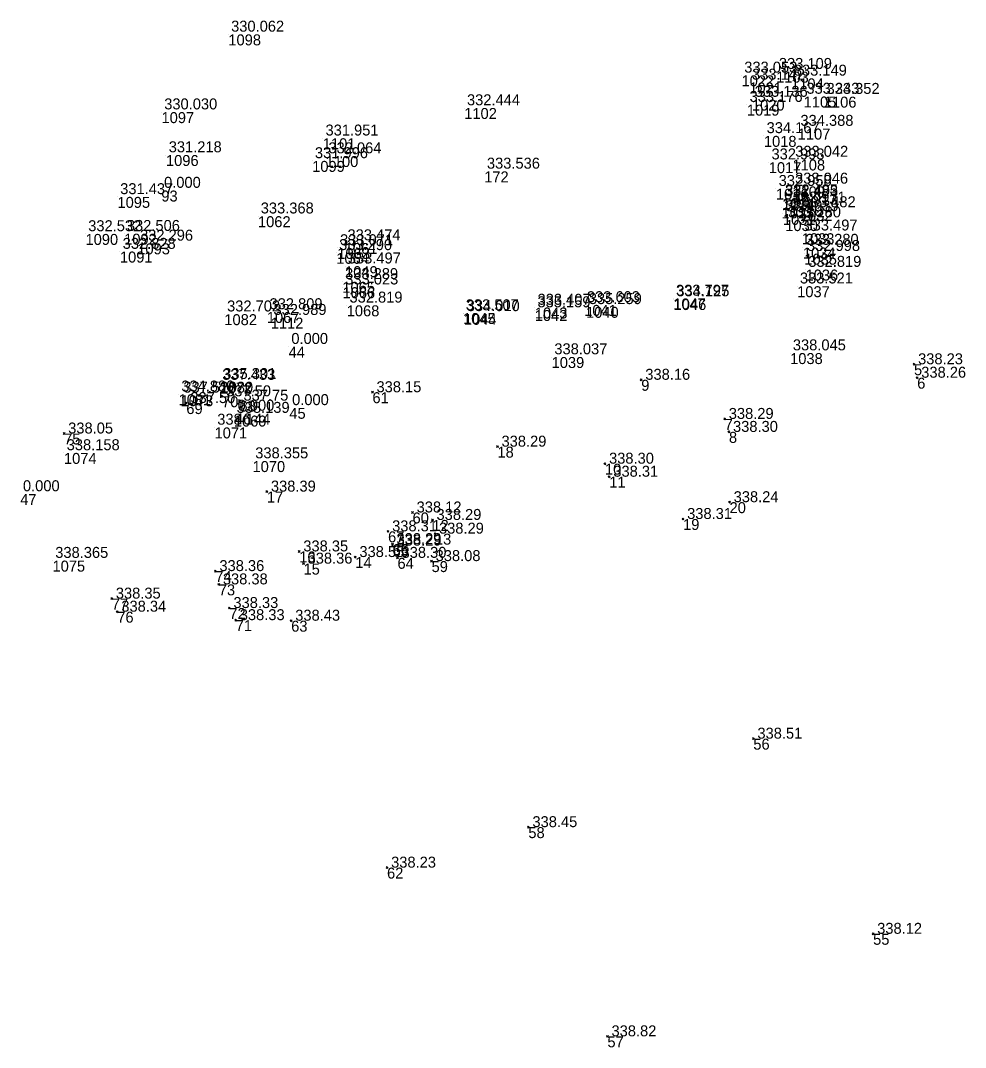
# Model space of a CAD drawing. Extents: x -829398 to -819400, y -1074439 to -1067977.
# Drawn here: x -825510.3 to -825406.9, y -1070192.8 to -1070080.5 of the extents above; entities that cross this region are included whole.
import ezdxf

# ---------------------------------------------------------------- set-up
doc = ezdxf.new("R2010")
doc.units = 0
doc.layers.add('Vrstva 60', color=7, linetype='Continuous')
doc.layers.add('Vrstva 61', color=7, linetype='Continuous')

msp = doc.modelspace()

# ---------------------------------------------------------------- linework, layer by layer
at = {"layer": 'Vrstva 60'}
for p, q in [((-825487.568, -1070081.975), (-825487.568, -1070081.975)), ((-825431.407, -1070086.457), (-825431.407, -1070086.457)), ((-825427.618, -1070086.054), (-825427.618, -1070086.054)), ((-825425.983, -1070086.788), (-825425.983, -1070086.788)), ((-825430.563, -1070087.234), (-825430.563, -1070087.234)), ((-825430.264, -1070089.105), (-825430.264, -1070089.105)), ((-825424.609, -1070088.772), (-825424.609, -1070088.772)), ((-825422.398, -1070088.786), (-825422.398, -1070088.786)), ((-825461.754, -1070090.029), (-825461.754, -1070090.029)), ((-825430.827, -1070089.662), (-825430.827, -1070089.662)), ((-825494.888, -1070090.481), (-825494.888, -1070090.481)), ((-825425.259, -1070092.281), (-825425.259, -1070092.281)), ((-825477.236, -1070093.341), (-825477.236, -1070093.341)), ((-825428.961, -1070093.081), (-825428.961, -1070093.081)), ((-825494.396, -1070095.175), (-825494.396, -1070095.175)), ((-825478.397, -1070095.821), (-825478.397, -1070095.821)), ((-825476.919, -1070095.288), (-825476.919, -1070095.288)), ((-825428.427, -1070095.957), (-825428.427, -1070095.957)), ((-825425.834, -1070095.665), (-825425.834, -1070095.665)), ((-825459.572, -1070096.967), (-825459.572, -1070096.967)), ((-825494.907, -1070099.064), (-825494.907, -1070099.064)), ((-825427.645, -1070098.86), (-825427.645, -1070098.86)), ((-825425.845, -1070098.607), (-825425.845, -1070098.607)), ((-825499.707, -1070099.758), (-825499.707, -1070099.758)), ((-825426.948, -1070099.886), (-825426.948, -1070099.886)), ((-825426.938, -1070099.975), (-825426.938, -1070099.975)), ((-825427.014, -1070100.906), (-825427.014, -1070100.906)), ((-825426.885, -1070101.627), (-825426.885, -1070101.627)), ((-825426.112, -1070100.679), (-825426.112, -1070100.679)), ((-825425.016, -1070101.189), (-825425.016, -1070101.189)), ((-825484.326, -1070101.871), (-825484.326, -1070101.871)), ((-825426.628, -1070102.296), (-825426.628, -1070102.296)), ((-825503.207, -1070103.813), (-825503.207, -1070103.813)), ((-825498.975, -1070103.784), (-825498.975, -1070103.784)), ((-825424.811, -1070103.736), (-825424.811, -1070103.736)), ((-825497.536, -1070104.845), (-825497.536, -1070104.845)), ((-825474.83, -1070104.805), (-825474.83, -1070104.805)), ((-825499.44, -1070105.742), (-825499.44, -1070105.742)), ((-825475.754, -1070105.88), (-825475.754, -1070105.88)), ((-825475.646, -1070105.345), (-825475.646, -1070105.345)), ((-825424.692, -1070105.301), (-825424.692, -1070105.301)), ((-825424.54, -1070105.973), (-825424.54, -1070105.973)), ((-825474.796, -1070107.341), (-825474.796, -1070107.341)), ((-825424.399, -1070107.713), (-825424.399, -1070107.713)), ((-825475.093, -1070109.051), (-825475.093, -1070109.051)), ((-825425.318, -1070109.533), (-825425.318, -1070109.533)), ((-825475.076, -1070109.642), (-825475.076, -1070109.642)), ((-825474.615, -1070111.623), (-825474.615, -1070111.623)), ((-825448.63, -1070111.58), (-825448.63, -1070111.58)), ((-825448.423, -1070111.789), (-825448.423, -1070111.789)), ((-825438.879, -1070110.871), (-825438.879, -1070110.871)), ((-825438.836, -1070110.937), (-825438.836, -1070110.937)), ((-825488.009, -1070112.593), (-825488.009, -1070112.593)), ((-825483.362, -1070112.349), (-825483.362, -1070112.349)), ((-825461.883, -1070112.464), (-825461.883, -1070112.464)), ((-825461.785, -1070112.557), (-825461.785, -1070112.557)), ((-825454.039, -1070112.137), (-825454.039, -1070112.137)), ((-825454.029, -1070111.862), (-825454.029, -1070111.862)), ((-825482.931, -1070112.976), (-825482.931, -1070112.976)), ((-825480.978, -1070116.15), (-825480.978, -1070116.15)), ((-825452.192, -1070117.281), (-825452.192, -1070117.281)), ((-825426.09, -1070116.851), (-825426.09, -1070116.851)), ((-825412.529, -1070118.074), (-825412.629, -1070117.974)), ((-825412.529, -1070118.074), (-825412.629, -1070118.174)), ((-825412.529, -1070118.074), (-825412.429, -1070117.974)), ((-825412.529, -1070118.074), (-825412.429, -1070118.174)), ((-825412.183, -1070119.545), (-825412.283, -1070119.445)), ((-825412.183, -1070119.545), (-825412.283, -1070119.645)), ((-825412.183, -1070119.545), (-825412.083, -1070119.445)), ((-825412.183, -1070119.545), (-825412.083, -1070119.645)), ((-825488.538, -1070120.077), (-825488.538, -1070120.077)), ((-825488.432, -1070119.984), (-825488.432, -1070119.984)), ((-825442.383, -1070119.773), (-825442.483, -1070119.673)), ((-825442.383, -1070119.773), (-825442.483, -1070119.873)), ((-825442.383, -1070119.773), (-825442.283, -1070119.673)), ((-825442.383, -1070119.773), (-825442.283, -1070119.873)), ((-825493.018, -1070121.358), (-825493.018, -1070121.358)), ((-825492.798, -1070121.473), (-825492.798, -1070121.473)), ((-825488.259, -1070121.578), (-825488.359, -1070121.478)), ((-825488.259, -1070121.578), (-825488.359, -1070121.678)), ((-825488.259, -1070121.578), (-825488.159, -1070121.478)), ((-825488.259, -1070121.578), (-825488.159, -1070121.678)), ((-825471.803, -1070121.133), (-825471.903, -1070121.033)), ((-825471.803, -1070121.133), (-825471.903, -1070121.233)), ((-825471.803, -1070121.133), (-825471.703, -1070121.033)), ((-825471.803, -1070121.133), (-825471.703, -1070121.233)), ((-825492.17, -1070122.322), (-825492.27, -1070122.222)), ((-825492.17, -1070122.322), (-825492.27, -1070122.422)), ((-825492.17, -1070122.322), (-825492.07, -1070122.222)), ((-825492.17, -1070122.322), (-825492.07, -1070122.422)), ((-825486.362, -1070122.053), (-825486.462, -1070121.953)), ((-825486.362, -1070122.053), (-825486.462, -1070122.153)), ((-825486.362, -1070122.053), (-825486.262, -1070121.953)), ((-825486.362, -1070122.053), (-825486.262, -1070122.153)), ((-825480.896, -1070122.842), (-825480.896, -1070122.842)), ((-825486.968, -1070123.69), (-825486.968, -1070123.69)), ((-825486.857, -1070123.456), (-825486.857, -1070123.456)), ((-825433.25, -1070124.055), (-825433.35, -1070123.955)), ((-825433.25, -1070124.055), (-825433.35, -1070124.155)), ((-825433.25, -1070124.055), (-825433.15, -1070123.955)), ((-825433.25, -1070124.055), (-825433.15, -1070124.155)), ((-825489.084, -1070124.987), (-825489.084, -1070124.987)), ((-825505.546, -1070125.652), (-825505.646, -1070125.552)), ((-825505.546, -1070125.652), (-825505.646, -1070125.752)), ((-825505.546, -1070125.652), (-825505.446, -1070125.552)), ((-825505.546, -1070125.652), (-825505.446, -1070125.752)), ((-825432.783, -1070125.475), (-825432.883, -1070125.375)), ((-825432.783, -1070125.475), (-825432.883, -1070125.575)), ((-825432.783, -1070125.475), (-825432.683, -1070125.375)), ((-825432.783, -1070125.475), (-825432.683, -1070125.575)), ((-825458.121, -1070127.09), (-825458.221, -1070126.99)), ((-825458.121, -1070127.09), (-825458.221, -1070127.19)), ((-825458.121, -1070127.09), (-825458.021, -1070126.99)), ((-825458.121, -1070127.09), (-825458.021, -1070127.19)), ((-825505.564, -1070127.779), (-825505.564, -1070127.779)), ((-825484.929, -1070128.668), (-825484.929, -1070128.668)), ((-825446.352, -1070128.954), (-825446.452, -1070128.854)), ((-825446.352, -1070128.954), (-825446.452, -1070129.054)), ((-825446.352, -1070128.954), (-825446.252, -1070128.854)), ((-825446.352, -1070128.954), (-825446.252, -1070129.054)), ((-825445.885, -1070130.381), (-825445.985, -1070130.281)), ((-825445.885, -1070130.381), (-825445.985, -1070130.481)), ((-825445.885, -1070130.381), (-825445.785, -1070130.281)), ((-825445.885, -1070130.381), (-825445.785, -1070130.481)), ((-825483.357, -1070132.007), (-825483.457, -1070131.907)), ((-825483.357, -1070132.007), (-825483.457, -1070132.107)), ((-825483.357, -1070132.007), (-825483.257, -1070131.907)), ((-825483.357, -1070132.007), (-825483.257, -1070132.107)), ((-825432.715, -1070133.167), (-825432.815, -1070133.067)), ((-825432.715, -1070133.167), (-825432.615, -1070133.067)), ((-825467.411, -1070134.292), (-825467.511, -1070134.192)), ((-825467.411, -1070134.292), (-825467.311, -1070134.192)), ((-825432.715, -1070133.167), (-825432.815, -1070133.267)), ((-825432.715, -1070133.167), (-825432.615, -1070133.267)), ((-825467.411, -1070134.292), (-825467.511, -1070134.392)), ((-825467.411, -1070134.292), (-825467.311, -1070134.392)), ((-825465.236, -1070135.109), (-825465.336, -1070135.009)), ((-825465.236, -1070135.109), (-825465.336, -1070135.209)), ((-825465.236, -1070135.109), (-825465.136, -1070135.009)), ((-825465.236, -1070135.109), (-825465.136, -1070135.209)), ((-825437.806, -1070135.008), (-825437.906, -1070134.908)), ((-825437.806, -1070135.008), (-825437.906, -1070135.108)), ((-825437.806, -1070135.008), (-825437.706, -1070134.908)), ((-825437.806, -1070135.008), (-825437.706, -1070135.108)), ((-825470.092, -1070136.359), (-825470.192, -1070136.259)), ((-825470.092, -1070136.359), (-825470.192, -1070136.459)), ((-825470.092, -1070136.359), (-825469.992, -1070136.259)), ((-825470.092, -1070136.359), (-825469.992, -1070136.459)), ((-825464.962, -1070136.611), (-825465.062, -1070136.511)), ((-825464.962, -1070136.611), (-825464.862, -1070136.511)), ((-825464.962, -1070136.611), (-825465.062, -1070136.711)), ((-825464.962, -1070136.611), (-825464.862, -1070136.711)), ((-825479.815, -1070138.556), (-825479.915, -1070138.456)), ((-825479.815, -1070138.556), (-825479.915, -1070138.656)), ((-825479.815, -1070138.556), (-825479.715, -1070138.456)), ((-825479.815, -1070138.556), (-825479.715, -1070138.656)), ((-825469.612, -1070137.755), (-825469.712, -1070137.655)), ((-825469.612, -1070137.755), (-825469.712, -1070137.855)), ((-825469.595, -1070137.915), (-825469.695, -1070137.815)), ((-825469.595, -1070137.915), (-825469.695, -1070138.015)), ((-825469.612, -1070137.755), (-825469.512, -1070137.655)), ((-825469.612, -1070137.755), (-825469.512, -1070137.855)), ((-825469.595, -1070137.915), (-825469.495, -1070137.815)), ((-825469.595, -1070137.915), (-825469.495, -1070138.015)), ((-825506.816, -1070139.563), (-825506.816, -1070139.563)), ((-825479.344, -1070139.892), (-825479.444, -1070139.792)), ((-825479.344, -1070139.892), (-825479.444, -1070139.992)), ((-825479.344, -1070139.892), (-825479.244, -1070139.792)), ((-825479.344, -1070139.892), (-825479.244, -1070139.992)), ((-825473.676, -1070139.171), (-825473.776, -1070139.071)), ((-825473.676, -1070139.171), (-825473.776, -1070139.271)), ((-825473.676, -1070139.171), (-825473.576, -1070139.071)), ((-825473.676, -1070139.171), (-825473.576, -1070139.271)), ((-825469.061, -1070139.258), (-825469.161, -1070139.158)), ((-825469.061, -1070139.258), (-825469.161, -1070139.358)), ((-825469.061, -1070139.258), (-825468.961, -1070139.158)), ((-825469.061, -1070139.258), (-825468.961, -1070139.358)), ((-825465.33, -1070139.615), (-825465.43, -1070139.515)), ((-825465.33, -1070139.615), (-825465.43, -1070139.715)), ((-825465.33, -1070139.615), (-825465.23, -1070139.515)), ((-825465.33, -1070139.615), (-825465.23, -1070139.715)), ((-825488.995, -1070140.71), (-825489.095, -1070140.61)), ((-825488.995, -1070140.71), (-825489.095, -1070140.81)), ((-825488.995, -1070140.71), (-825488.895, -1070140.61)), ((-825488.995, -1070140.71), (-825488.895, -1070140.81)), ((-825488.617, -1070142.164), (-825488.717, -1070142.064)), ((-825488.617, -1070142.164), (-825488.517, -1070142.064)), ((-825488.617, -1070142.164), (-825488.717, -1070142.264)), ((-825488.617, -1070142.164), (-825488.517, -1070142.264)), ((-825500.331, -1070143.719), (-825500.431, -1070143.619)), ((-825500.331, -1070143.719), (-825500.431, -1070143.819)), ((-825500.331, -1070143.719), (-825500.231, -1070143.619)), ((-825500.331, -1070143.719), (-825500.231, -1070143.819)), ((-825499.728, -1070145.15), (-825499.828, -1070145.05)), ((-825499.728, -1070145.15), (-825499.828, -1070145.25)), ((-825499.728, -1070145.15), (-825499.628, -1070145.05)), ((-825499.728, -1070145.15), (-825499.628, -1070145.25)), ((-825487.463, -1070144.752), (-825487.563, -1070144.652)), ((-825487.463, -1070144.752), (-825487.563, -1070144.852)), ((-825487.463, -1070144.752), (-825487.363, -1070144.652)), ((-825487.463, -1070144.752), (-825487.363, -1070144.852)), ((-825486.768, -1070146.078), (-825486.868, -1070145.978)), ((-825486.768, -1070146.078), (-825486.868, -1070146.178)), ((-825486.768, -1070146.078), (-825486.668, -1070145.978)), ((-825486.768, -1070146.078), (-825486.668, -1070146.178)), ((-825480.695, -1070146.138), (-825480.795, -1070146.038)), ((-825480.695, -1070146.138), (-825480.795, -1070146.238)), ((-825480.695, -1070146.138), (-825480.595, -1070146.038)), ((-825480.695, -1070146.138), (-825480.595, -1070146.238)), ((-825430.115, -1070159.047), (-825430.215, -1070158.947)), ((-825430.115, -1070159.047), (-825430.015, -1070158.947)), ((-825430.115, -1070159.047), (-825430.215, -1070159.147)), ((-825430.115, -1070159.047), (-825430.015, -1070159.147)), ((-825454.738, -1070168.732), (-825454.838, -1070168.632)), ((-825454.738, -1070168.732), (-825454.838, -1070168.832)), ((-825454.738, -1070168.732), (-825454.638, -1070168.632)), ((-825454.738, -1070168.732), (-825454.638, -1070168.832)), ((-825470.203, -1070173.16), (-825470.303, -1070173.06)), ((-825470.203, -1070173.16), (-825470.303, -1070173.26)), ((-825470.203, -1070173.16), (-825470.103, -1070173.06)), ((-825470.203, -1070173.16), (-825470.103, -1070173.26)), ((-825417.006, -1070180.403), (-825417.106, -1070180.303)), ((-825417.006, -1070180.403), (-825416.906, -1070180.303)), ((-825417.006, -1070180.403), (-825417.106, -1070180.503)), ((-825417.006, -1070180.403), (-825416.906, -1070180.503)), ((-825446.083, -1070191.624), (-825446.183, -1070191.524)), ((-825446.083, -1070191.624), (-825445.983, -1070191.524)), ((-825446.083, -1070191.624), (-825446.183, -1070191.724)), ((-825446.083, -1070191.624), (-825445.983, -1070191.724))]:
    msp.add_line(p, q, dxfattribs=at)

# ---------------------------------------------------------------- texts
for s, p in [('1098', (-825487.568, -1070083.175)), ('1022', (-825431.407, -1070087.657)), ('1103', (-825427.618, -1070087.254)), ('1104', (-825425.983, -1070087.988)), ('1021', (-825430.563, -1070088.434)), ('1020', (-825430.264, -1070090.305)), ('1105', (-825424.609, -1070089.972)), ('1106', (-825422.398, -1070089.986)), ('1102', (-825461.754, -1070091.229)), ('1019', (-825430.827, -1070090.862)), ('1097', (-825494.888, -1070091.681)), ('1107', (-825425.259, -1070093.481)), ('1101', (-825477.236, -1070094.541)), ('1018', (-825428.961, -1070094.281)), ('1096', (-825494.396, -1070096.375)), ('1099', (-825478.397, -1070097.021)), ('1100', (-825476.919, -1070096.488)), ('1017', (-825428.427, -1070097.157)), ('1108', (-825425.834, -1070096.865)), ('172', (-825459.572, -1070098.167)), ('93', (-825494.907, -1070100.264)), ('1016', (-825427.645, -1070100.06)), ('1109', (-825425.845, -1070099.807)), ('1095', (-825499.707, -1070100.958)), ('1014', (-825426.948, -1070101.086)), ('1111', (-825426.938, -1070101.175)), ('1015', (-825427.014, -1070102.106)), ('1031', (-825426.885, -1070102.827)), ('1110', (-825426.112, -1070101.879)), ('1032', (-825425.016, -1070102.389)), ('1062', (-825484.326, -1070103.071)), ('1030', (-825426.628, -1070103.496)), ('1090', (-825503.207, -1070105.013)), ('1092', (-825498.975, -1070104.984)), ('1033', (-825424.811, -1070104.936)), ('1093', (-825497.536, -1070106.045)), ('1061', (-825474.83, -1070106.005)), ('1091', (-825499.44, -1070106.942)), ('1064', (-825475.754, -1070107.08)), ('1063', (-825475.646, -1070106.545)), ('1034', (-825424.692, -1070106.501)), ('1035', (-825424.54, -1070107.173)), ('1049', (-825474.796, -1070108.541)), ('1036', (-825424.399, -1070108.913)), ('1065', (-825475.093, -1070110.251)), ('1037', (-825425.318, -1070110.733)), ('1066', (-825475.076, -1070110.842)), ('1068', (-825474.615, -1070112.823)), ('1041', (-825448.63, -1070112.78)), ('1040', (-825448.423, -1070112.989)), ('1047', (-825438.879, -1070112.071)), ('1046', (-825438.836, -1070112.137)), ('1082', (-825488.009, -1070113.793)), ('1067', (-825483.362, -1070113.549)), ('1045', (-825461.883, -1070113.664)), ('1044', (-825461.785, -1070113.757)), ('1042', (-825454.039, -1070113.337)), ('1043', (-825454.029, -1070113.062)), ('1112', (-825482.931, -1070114.176)), ('44', (-825480.978, -1070117.35)), ('1039', (-825452.192, -1070118.481)), ('1038', (-825426.09, -1070118.051)), ('5', (-825412.529, -1070119.274)), ('6', (-825412.183, -1070120.745)), ('1072', (-825488.538, -1070121.277)), ('1080', (-825488.432, -1070121.184)), ('9', (-825442.383, -1070120.973)), ('1081', (-825493.018, -1070122.558)), ('1073', (-825492.798, -1070122.673)), ('70', (-825488.259, -1070122.778)), ('61', (-825471.803, -1070122.333)), ('69', (-825492.17, -1070123.522)), ('68', (-825486.362, -1070123.253)), ('45', (-825480.896, -1070124.042)), ('1069', (-825486.968, -1070124.89)), ('46', (-825486.857, -1070124.656)), ('7', (-825433.25, -1070125.255)), ('1071', (-825489.084, -1070126.187)), ('75', (-825505.546, -1070126.852)), ('8', (-825432.783, -1070126.675)), ('18', (-825458.121, -1070128.29)), ('1074', (-825505.564, -1070128.979)), ('1070', (-825484.929, -1070129.868)), ('10', (-825446.352, -1070130.154)), ('11', (-825445.885, -1070131.581)), ('17', (-825483.357, -1070133.207)), ('47', (-825510.352, -1070133.47)), ('20', (-825432.715, -1070134.367)), ('60', (-825467.411, -1070135.492)), ('12', (-825465.236, -1070136.309)), ('19', (-825437.806, -1070136.208)), ('67', (-825470.092, -1070137.559)), ('13', (-825464.962, -1070137.811)), ('16', (-825479.815, -1070139.756)), ('66', (-825469.612, -1070138.955)), ('65', (-825469.595, -1070139.115)), ('1075', (-825506.816, -1070140.763)), ('15', (-825479.344, -1070141.092)), ('14', (-825473.676, -1070140.371)), ('64', (-825469.061, -1070140.458)), ('59', (-825465.33, -1070140.815)), ('74', (-825488.995, -1070141.91)), ('73', (-825488.617, -1070143.364)), ('77', (-825500.331, -1070144.919)), ('76', (-825499.728, -1070146.35)), ('72', (-825487.463, -1070145.952)), ('71', (-825486.768, -1070147.278)), ('63', (-825480.695, -1070147.338)), ('56', (-825430.115, -1070160.247)), ('58', (-825454.738, -1070169.932)), ('62', (-825470.203, -1070174.36)), ('55', (-825417.006, -1070181.603)), ('57', (-825446.083, -1070192.824))]:
    msp.add_text(s, height=1.2, dxfattribs=at).set_placement(p)
at = {"layer": 'Vrstva 61'}
for s, p in [('330.062', (-825487.268, -1070081.675)), ('333.109', (-825427.318, -1070085.754)), ('333.053', (-825431.107, -1070086.157)), ('333.142', (-825430.263, -1070086.934)), ('333.149', (-825425.683, -1070086.488)), ('333.176', (-825430.527, -1070089.362)), ('333.136', (-825429.964, -1070088.805)), ('333.243', (-825424.309, -1070088.472)), ('333.352', (-825422.098, -1070088.486)), ('330.030', (-825494.588, -1070090.181)), ('332.444', (-825461.454, -1070089.729)), ('334.167', (-825428.661, -1070092.781)), ('334.388', (-825424.959, -1070091.981)), ('331.951', (-825476.936, -1070093.041)), ('331.218', (-825494.096, -1070094.875)), ('332.064', (-825476.619, -1070094.988)), ('331.996', (-825478.097, -1070095.521)), ('332.993', (-825428.127, -1070095.657)), ('333.042', (-825425.534, -1070095.365)), ('333.536', (-825459.272, -1070096.667)), ('333.046', (-825425.545, -1070098.307)), ('331.437', (-825499.407, -1070099.458)), ('0.000', (-825494.607, -1070098.764)), ('332.958', (-825427.345, -1070098.56)), ('332.913', (-825426.714, -1070100.606)), ('332.485', (-825426.648, -1070099.586)), ('332.493', (-825426.638, -1070099.675)), ('332.971', (-825425.812, -1070100.379)), ('333.368', (-825484.026, -1070101.571)), ('333.039', (-825426.585, -1070101.327)), ('333.482', (-825424.716, -1070100.889)), ('333.280', (-825426.328, -1070101.996)), ('332.532', (-825502.907, -1070103.513)), ('332.506', (-825498.675, -1070103.484)), ('333.497', (-825424.511, -1070103.436)), ('332.296', (-825497.236, -1070104.545)), ('333.071', (-825475.346, -1070105.045)), ('333.474', (-825474.53, -1070104.505)), ('333.280', (-825424.392, -1070105.001)), ('332.828', (-825499.14, -1070105.442)), ('333.290', (-825475.454, -1070105.58)), ('332.998', (-825424.24, -1070105.673)), ('333.497', (-825474.496, -1070107.041)), ('332.819', (-825424.099, -1070107.413)), ('333.289', (-825474.793, -1070108.751)), ('333.023', (-825474.776, -1070109.342)), ('333.521', (-825425.018, -1070109.233)), ('333.797', (-825438.579, -1070110.571)), ('334.125', (-825438.536, -1070110.637)), ('332.819', (-825474.315, -1070111.323)), ('335.159', (-825453.739, -1070111.837)), ('333.407', (-825453.729, -1070111.562)), ('333.603', (-825448.33, -1070111.28)), ('335.259', (-825448.123, -1070111.489)), ('332.702', (-825487.709, -1070112.293)), ('332.809', (-825483.062, -1070112.049)), ('332.989', (-825482.631, -1070112.676)), ('333.507', (-825461.583, -1070112.164)), ('334.010', (-825461.485, -1070112.257)), ('0.000', (-825480.678, -1070115.85)), ('338.037', (-825451.892, -1070116.981)), ('338.045', (-825425.79, -1070116.551)), (' 338.23', (-825412.529, -1070118.074)), ('335.301', (-825488.132, -1070119.684)), (' 338.26', (-825412.183, -1070119.545)), ('337.433', (-825488.238, -1070119.777)), (' 338.16', (-825442.383, -1070119.773)), ('334.880', (-825492.718, -1070121.058)), ('337.528', (-825492.498, -1070121.173)), (' 337.50', (-825488.259, -1070121.578)), (' 338.15', (-825471.803, -1070121.133)), (' 337.50', (-825492.17, -1070122.322)), (' 337.75', (-825486.362, -1070122.053)), ('0.000', (-825480.596, -1070122.542)), ('338.139', (-825486.668, -1070123.39)), ('0.000', (-825486.557, -1070123.156)), (' 338.29', (-825433.25, -1070124.055)), ('338.144', (-825488.784, -1070124.687)), (' 338.05', (-825505.546, -1070125.652)), (' 338.30', (-825432.783, -1070125.475)), ('338.158', (-825505.264, -1070127.479)), (' 338.29', (-825458.121, -1070127.09)), ('338.355', (-825484.629, -1070128.368)), (' 338.30', (-825446.352, -1070128.954)), (' 338.31', (-825445.885, -1070130.381)), ('0.000', (-825510.052, -1070131.97)), (' 338.39', (-825483.357, -1070132.007)), (' 338.24', (-825432.715, -1070133.167)), (' 338.12', (-825467.411, -1070134.292)), (' 338.29', (-825465.236, -1070135.109)), (' 338.31', (-825437.806, -1070135.008)), (' 338.31', (-825470.092, -1070136.359)), (' 338.29', (-825464.962, -1070136.611)), (' 338.35', (-825479.815, -1070138.556)), (' 338.29', (-825469.612, -1070137.755)), (' 338.29', (-825469.595, -1070137.915)), ('338.365', (-825506.516, -1070139.263)), (' 338.36', (-825479.344, -1070139.892)), (' 338.55', (-825473.676, -1070139.171)), (' 338.30', (-825469.061, -1070139.258)), (' 338.08', (-825465.33, -1070139.615)), (' 338.36', (-825488.995, -1070140.71)), (' 338.38', (-825488.617, -1070142.164)), (' 338.35', (-825500.331, -1070143.719)), (' 338.34', (-825499.728, -1070145.15)), (' 338.33', (-825487.463, -1070144.752)), (' 338.33', (-825486.768, -1070146.078)), (' 338.43', (-825480.695, -1070146.138)), (' 338.51', (-825430.115, -1070159.047)), (' 338.45', (-825454.738, -1070168.732)), (' 338.23', (-825470.203, -1070173.16)), (' 338.12', (-825417.006, -1070180.403)), (' 338.82', (-825446.083, -1070191.624))]:
    msp.add_text(s, height=1.2, dxfattribs=at).set_placement(p)

doc.saveas('drawing.dxf')
